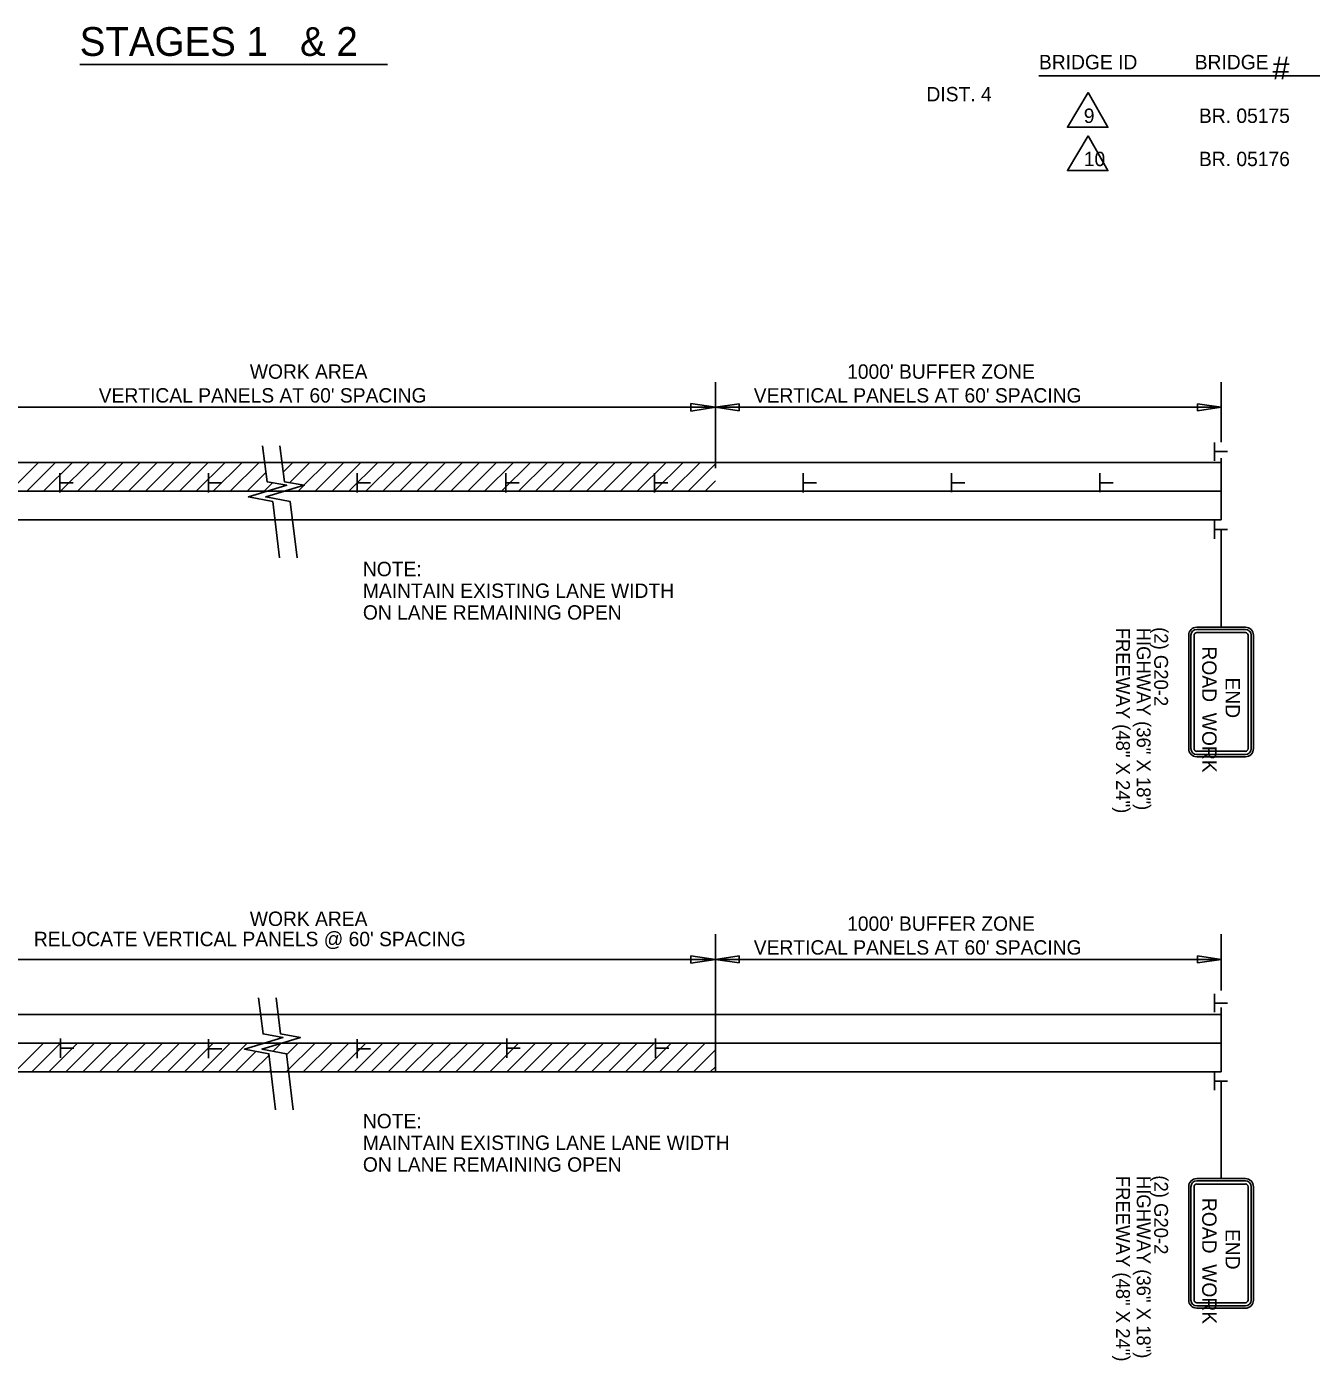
# Model space of a CAD drawing. Extents: x 1930579 to 1937521, y 596183 to 597599.
# Drawn here: x 1935668 to 1936204, y 596332 to 596888 of the extents above; entities that cross this region are included whole.
import ezdxf

# ---------------------------------------------------------------- set-up
doc = ezdxf.new("R2010")
doc.units = 0
for name, color, linetype in [('Default', 7, 'Continuous'), ('P_TC_Signs_Temporary', 7, 'Continuous'), ('R_Annotation', 7, 'Continuous')]:
    doc.layers.add(name, color=color, linetype=linetype)

msp = doc.modelspace()

# ---------------------------------------------------------------- linework, layer by layer
at = {"layer": 'Default'}
for p, q in [((1935690.44, 596872.49), (1935818.76, 596872.49)), ((1935955.49, 596740.12), (1935955.49, 596704.24)), ((1936166.23, 596740.12), (1936166.23, 596715.05)), ((1935955.49, 596729.59), (1935620.14, 596729.59)), ((1935945.19, 596728.04), (1935945.19, 596731.13)), ((1935945.19, 596731.13), (1935955.49, 596729.59)), ((1935955.49, 596729.59), (1935945.19, 596728.04)), ((1935955.49, 596729.59), (1935965.38, 596731.08)), ((1936166.23, 596729.59), (1935955.49, 596729.59)), ((1935965.38, 596728.11), (1935955.49, 596729.59)), ((1935965.38, 596731.08), (1935965.38, 596728.11)), ((1936156.33, 596728.11), (1936156.33, 596731.08)), ((1936156.33, 596731.08), (1936166.23, 596729.59)), ((1936156.33, 596728.11), (1936156.33, 596731.08)), ((1936156.33, 596731.08), (1936166.23, 596729.59)), ((1936166.23, 596729.59), (1936156.33, 596728.11)), ((1936166.23, 596729.59), (1936156.33, 596728.11)), ((1936163.5, 596714.95), (1936163.5, 596707.29)), ((1936163.61, 596711.14), (1936168.84, 596711.14)), ((1936166.23, 596706.66), (1935116.21, 596706.66)), ((1935661.26, 596694.66), (1935673.26, 596706.66)), ((1935668.34, 596694.66), (1935680.34, 596706.66)), ((1935675.41, 596694.66), (1935687.41, 596706.66)), ((1935682.48, 596694.66), (1935694.48, 596706.66)), ((1935689.55, 596694.66), (1935701.55, 596706.66)), ((1935696.62, 596694.66), (1935708.62, 596706.66)), ((1935703.69, 596694.66), (1935715.69, 596706.66)), ((1935710.76, 596694.66), (1935722.76, 596706.66)), ((1935717.83, 596694.66), (1935729.83, 596706.66)), ((1935724.9, 596694.66), (1935736.9, 596706.66)), ((1935731.98, 596694.66), (1935743.98, 596706.66)), ((1935739.05, 596694.66), (1935751.05, 596706.66)), ((1935746.12, 596694.66), (1935758.12, 596706.66)), ((1935753.19, 596694.66), (1935765.19, 596706.66)), ((1935775.29, 596702.63), (1935779.33, 596706.66)), ((1935777.92, 596698.18), (1935786.4, 596706.66)), ((1935783.93, 596697.11), (1935793.47, 596706.66)), ((1935788.54, 596694.66), (1935800.54, 596706.66)), ((1935795.62, 596694.66), (1935807.62, 596706.66)), ((1935802.69, 596694.66), (1935814.69, 596706.66)), ((1935809.76, 596694.66), (1935821.76, 596706.66)), ((1935816.83, 596694.66), (1935828.83, 596706.66)), ((1935823.9, 596694.66), (1935835.9, 596706.66)), ((1935830.97, 596694.66), (1935842.97, 596706.66)), ((1935838.04, 596694.66), (1935850.04, 596706.66)), ((1935845.11, 596694.66), (1935857.11, 596706.66)), ((1935852.18, 596694.66), (1935864.18, 596706.66)), ((1935859.25, 596694.66), (1935871.25, 596706.66)), ((1935866.33, 596694.66), (1935878.33, 596706.66)), ((1935873.4, 596694.66), (1935885.4, 596706.66)), ((1935880.47, 596694.66), (1935892.47, 596706.66)), ((1935887.54, 596694.66), (1935899.54, 596706.66)), ((1935894.61, 596694.66), (1935906.61, 596706.66)), ((1935901.68, 596694.66), (1935913.68, 596706.66)), ((1935908.75, 596694.66), (1935920.75, 596706.66)), ((1935915.82, 596694.66), (1935927.82, 596706.66)), ((1935922.89, 596694.66), (1935934.89, 596706.66)), ((1935929.97, 596694.66), (1935941.97, 596706.66)), ((1935937.04, 596694.66), (1935949.04, 596706.66)), ((1935944.11, 596694.66), (1935955.49, 596706.05)), ((1936166.23, 596708.38), (1936166.23, 596682.66)), ((1935682.13, 596694.12), (1935682.13, 596702.1)), ((1935744.13, 596694.12), (1935744.13, 596702.1)), ((1935760.26, 596694.66), (1935768.03, 596702.44)), ((1935806.12, 596694.12), (1935806.12, 596702.1)), ((1935868.11, 596694.12), (1935868.11, 596702.1)), ((1935930.1, 596694.12), (1935930.1, 596702.1)), ((1935991.98, 596694.14), (1935991.98, 596702.12)), ((1936053.85, 596694.17), (1936053.85, 596702.15)), ((1936115.73, 596694.19), (1936115.73, 596702.17)), ((1935116.21, 596694.66), (1936166.23, 596694.66)), ((1935682.25, 596698.09), (1935687.7, 596698.09)), ((1935744.24, 596698.09), (1935749.69, 596698.09)), ((1935767.33, 596694.66), (1935770.81, 596698.14)), ((1935781.47, 596694.66), (1935783.83, 596697.02)), ((1935806.24, 596698.09), (1935811.68, 596698.09)), ((1935868.23, 596698.09), (1935873.67, 596698.09)), ((1935930.22, 596698.09), (1935935.67, 596698.09)), ((1935951.18, 596694.66), (1935955.49, 596698.97)), ((1935992.09, 596698.11), (1935997.54, 596698.11)), ((1936053.97, 596698.13), (1936059.42, 596698.13)), ((1936115.84, 596698.16), (1936121.29, 596698.16)), ((1936166.23, 596682.66), (1935116.21, 596682.66)), ((1935619.93, 596682.66), (1935770.53, 596682.66)), ((1935778.18, 596682.66), (1935955.49, 596682.66)), ((1936163.5, 596682.43), (1936163.5, 596674.76)), ((1936163.61, 596678.62), (1936168.84, 596678.62)), ((1935955.49, 596510.03), (1935955.49, 596452.57)), ((1935955.49, 596510.03), (1935955.49, 596474.15)), ((1936166.23, 596510.03), (1936166.23, 596486.53)), ((1935945.19, 596497.95), (1935945.19, 596501.04)), ((1935945.19, 596501.04), (1935955.49, 596499.5)), ((1935955.49, 596499.5), (1935965.38, 596500.98)), ((1935965.38, 596500.98), (1935965.38, 596498.01)), ((1936156.33, 596498.01), (1936156.33, 596500.98)), ((1936156.33, 596500.98), (1936166.23, 596499.5)), ((1936156.33, 596498.01), (1936156.33, 596500.98)), ((1936156.33, 596500.98), (1936166.23, 596499.5)), ((1935955.49, 596499.5), (1935620.14, 596499.5)), ((1935955.49, 596499.5), (1935945.19, 596497.95)), ((1936166.23, 596499.5), (1935955.49, 596499.5)), ((1935965.38, 596498.01), (1935955.49, 596499.5)), ((1936166.23, 596499.5), (1936156.33, 596498.01)), ((1936166.23, 596499.5), (1936156.33, 596498.01)), ((1936163.5, 596485.1), (1936163.5, 596477.44)), ((1936163.61, 596481.3), (1936168.84, 596481.3)), ((1936166.23, 596479.48), (1936166.23, 596452.57)), ((1936166.23, 596476.57), (1935116.21, 596476.57)), ((1935682.46, 596458.49), (1935682.46, 596466.46)), ((1935868.43, 596458.49), (1935868.43, 596466.46)), ((1935930.42, 596458.49), (1935930.42, 596466.46)), ((1935116.21, 596464.57), (1936166.23, 596464.57)), ((1935663.41, 596452.57), (1935675.41, 596464.57)), ((1935670.48, 596452.57), (1935682.48, 596464.57)), ((1935677.55, 596452.57), (1935689.55, 596464.57)), ((1935682.57, 596462.45), (1935688.02, 596462.45)), ((1935684.62, 596452.57), (1935696.62, 596464.57)), ((1935691.69, 596452.57), (1935703.69, 596464.57)), ((1935698.76, 596452.57), (1935710.76, 596464.57)), ((1935705.83, 596452.57), (1935717.83, 596464.57)), ((1935712.9, 596452.57), (1935724.9, 596464.57)), ((1935719.98, 596452.57), (1935731.98, 596464.57)), ((1935727.05, 596452.57), (1935739.05, 596464.57)), ((1935734.12, 596452.57), (1935746.12, 596464.57)), ((1935741.19, 596452.57), (1935753.19, 596464.57)), ((1935744.13, 596458.29), (1935744.13, 596466.27)), ((1935744.24, 596462.26), (1935749.69, 596462.26)), ((1935748.26, 596452.57), (1935760.26, 596464.57)), ((1935755.33, 596452.57), (1935763.97, 596461.21)), ((1935771.08, 596461.25), (1935774.4, 596464.57)), ((1935776.54, 596452.57), (1935788.54, 596464.57)), ((1935776.65, 596459.74), (1935781.47, 596464.57)), ((1935783.62, 596452.57), (1935795.62, 596464.57)), ((1935790.69, 596452.57), (1935802.69, 596464.57)), ((1935797.76, 596452.57), (1935809.76, 596464.57)), ((1935804.83, 596452.57), (1935816.83, 596464.57)), ((1935806.12, 596458.29), (1935806.12, 596466.27)), ((1935806.24, 596462.26), (1935811.68, 596462.26)), ((1935811.9, 596452.57), (1935823.9, 596464.57)), ((1935818.97, 596452.57), (1935830.97, 596464.57)), ((1935826.04, 596452.57), (1935838.04, 596464.57)), ((1935833.11, 596452.57), (1935845.11, 596464.57)), ((1935840.18, 596452.57), (1935852.18, 596464.57)), ((1935847.25, 596452.57), (1935859.25, 596464.57)), ((1935854.33, 596452.57), (1935866.33, 596464.57)), ((1935861.4, 596452.57), (1935873.4, 596464.57)), ((1935868.47, 596452.57), (1935880.47, 596464.57)), ((1935868.55, 596462.45), (1935874, 596462.45)), ((1935875.54, 596452.57), (1935887.54, 596464.57)), ((1935882.61, 596452.57), (1935894.61, 596464.57)), ((1935889.68, 596452.57), (1935901.68, 596464.57)), ((1935896.75, 596452.57), (1935908.75, 596464.57)), ((1935903.82, 596452.57), (1935915.82, 596464.57)), ((1935910.89, 596452.57), (1935922.89, 596464.57)), ((1935917.97, 596452.57), (1935929.97, 596464.57)), ((1935925.04, 596452.57), (1935937.04, 596464.57)), ((1935930.54, 596462.45), (1935935.99, 596462.45)), ((1935932.11, 596452.57), (1935944.11, 596464.57)), ((1935939.18, 596452.57), (1935951.18, 596464.57)), ((1935946.25, 596452.57), (1935955.49, 596461.81)), ((1935762.4, 596452.57), (1935769.39, 596459.55)), ((1936166.23, 596452.57), (1935116.21, 596452.57)), ((1935619.93, 596452.57), (1935770.53, 596452.57)), ((1935769.47, 596452.57), (1935770.14, 596453.24)), ((1935778.18, 596452.57), (1935955.49, 596452.57)), ((1935953.32, 596452.57), (1935955.49, 596454.74)), ((1936163.5, 596452.58), (1936163.5, 596444.92)), ((1936163.61, 596448.77), (1936168.84, 596448.77))]:
    msp.add_line(p, q, dxfattribs=at)
for points in [[(1935766.64, 596713.56), (1935768.52, 596698.55), (1935776.78, 596697.09), (1935760.75, 596692.23), (1935770.95, 596690.29), (1935773.76, 596666.9)], [(1935773.93, 596713.56), (1935775.8, 596698.55), (1935784.06, 596697.09), (1935768.03, 596692.23), (1935778.23, 596690.29), (1935781.05, 596666.9)], [(1935765, 596483.47), (1935766.88, 596468.46), (1935775.14, 596467), (1935759.11, 596462.14), (1935769.31, 596460.2), (1935772.12, 596436.81)], [(1935772.29, 596483.47), (1935774.16, 596468.46), (1935782.42, 596467), (1935766.39, 596462.14), (1935776.59, 596460.2), (1935779.41, 596436.81)]]:
    msp.add_lwpolyline(points, dxfattribs=at)
at = {"layer": 'P_TC_Signs_Temporary'}
for p, q in [((1936152.73, 596634.59), (1936152.73, 596587.34)), ((1936153.66, 596634.59), (1936153.66, 596587.34)), ((1936154.98, 596634.59), (1936154.98, 596587.34)), ((1936176.35, 596637.97), (1936156.1, 596637.97)), ((1936176.35, 596637.03), (1936156.1, 596637.03)), ((1936176.35, 596635.72), (1936156.1, 596635.72)), ((1936177.48, 596587.34), (1936177.48, 596634.59)), ((1936178.79, 596587.34), (1936178.79, 596634.59)), ((1936179.73, 596587.34), (1936179.73, 596634.59)), ((1936156.1, 596586.22), (1936176.35, 596586.22)), ((1936156.1, 596584.9), (1936176.35, 596584.9)), ((1936156.1, 596583.97), (1936176.35, 596583.97)), ((1936176.35, 596408.12), (1936156.1, 596408.12)), ((1936176.35, 596407.18), (1936156.1, 596407.18)), ((1936176.35, 596405.87), (1936156.1, 596405.87)), ((1936152.73, 596404.75), (1936152.73, 596357.5)), ((1936153.66, 596404.75), (1936153.66, 596357.5)), ((1936154.98, 596404.75), (1936154.98, 596357.5)), ((1936177.48, 596357.5), (1936177.48, 596404.75)), ((1936178.79, 596357.5), (1936178.79, 596404.75)), ((1936179.73, 596357.5), (1936179.73, 596404.75)), ((1936156.1, 596356.37), (1936176.35, 596356.37)), ((1936156.1, 596355.06), (1936176.35, 596355.06)), ((1936156.1, 596354.12), (1936176.35, 596354.12))]:
    msp.add_line(p, q, dxfattribs=at)
for centre, radius, start, end in [((1936156.1, 596634.59), 3.37, 90, 180), ((1936156.1, 596634.59), 2.44, 90, 180), ((1936156.1, 596634.59), 1.13, 90, 180), ((1936176.35, 596634.59), 3.37, 360, 90), ((1936176.35, 596634.59), 2.44, 360, 90), ((1936176.35, 596634.59), 1.13, 360, 90), ((1936156.1, 596587.34), 3.37, 180, 270), ((1936156.1, 596587.34), 2.44, 180, 270), ((1936156.1, 596587.34), 1.13, 180, 270), ((1936176.35, 596587.34), 2.44, 270, 360), ((1936176.35, 596587.34), 1.13, 270, 360), ((1936176.35, 596587.34), 3.38, 270, 360), ((1936156.1, 596404.75), 3.37, 90, 180), ((1936156.1, 596404.75), 2.44, 90, 180), ((1936156.1, 596404.75), 1.13, 90, 180), ((1936176.35, 596404.75), 3.37, 360, 90), ((1936176.35, 596404.75), 2.44, 360, 90), ((1936176.35, 596404.75), 1.13, 360, 90), ((1936156.1, 596357.5), 3.37, 180, 270), ((1936156.1, 596357.5), 2.44, 180, 270), ((1936156.1, 596357.5), 1.13, 180, 270), ((1936176.35, 596357.5), 2.44, 270, 360), ((1936176.35, 596357.5), 1.13, 270, 360), ((1936176.35, 596357.5), 3.38, 270, 360)]:
    msp.add_arc(centre, radius, start, end, dxfattribs=at)
at = {"layer": 'R_Annotation'}
for p, q in [((1936090.31, 596867.77), (1936637.5, 596867.77)), ((1936166.23, 596637.97), (1936166.23, 596678.62)), ((1936166.23, 596408.12), (1936166.23, 596448.77))]:
    msp.add_line(p, q, dxfattribs=at)
for points in [[(1936110.88, 596860.76), (1936102.16, 596846.29), (1936119.05, 596846.29), (1936110.88, 596860.76)], [(1936110.88, 596842.76), (1936102.16, 596828.29), (1936119.05, 596828.29), (1936110.88, 596842.76)]]:
    msp.add_lwpolyline(points, dxfattribs=at)

# ---------------------------------------------------------------- texts
at = {"layer": 'Default'}
for s, height, p in [('STAGES 1   & 2', 12, (1935690.44, 596876.06)), ('WORK AREA', 6, (1935761.36, 596741.5)), ("1000' BUFFER ZONE", 6, (1936010.35, 596741.5)), ("VERTICAL PANELS AT 60' SPACING", 5.9999, (1935698.38, 596731.57)), ("VERTICAL PANELS AT 60' SPACING", 5.9999, (1935971.43, 596731.57)), ('WORK AREA', 6, (1935761.36, 596513.43)), ("1000' BUFFER ZONE", 6, (1936010.35, 596511.41)), ("RELOCATE VERTICAL PANELS @ 60' SPACING", 6, (1935671.34, 596505)), ("VERTICAL PANELS AT 60' SPACING", 5.9999, (1935971.43, 596501.48))]:
    msp.add_text(s, height=height, rotation=360, dxfattribs=at).set_placement(p)
at = {"layer": 'P_TC_Signs_Temporary'}
for s, p in [('ROAD  WORK', (1936158.35, 596629.93)), ('END', (1936168.1, 596617)), ('ROAD  WORK', (1936158.35, 596400.08)), ('END', (1936168.1, 596387.15))]:
    msp.add_text(s, height=6, rotation=270, dxfattribs=at).set_placement(p)
at = {"layer": 'R_Annotation'}
for s, height, rotation, p in [('BRIDGE ID', 6, 360, (1936090.31, 596870.47)), ('BRIDGE ', 6, 360, (1936155.25, 596870.47)), ('#', 9.6, 360, (1936187.67, 596866.23)), ('DIST. 4', 6, 360, (1936043.41, 596857.12)), ('9', 6, 360, (1936109, 596848.12)), ('BR. 05175', 6, 360, (1936157, 596848.12)), ('10', 6, 360, (1936109, 596830.12)), ('BR. 05176', 6, 360, (1936157, 596830.12)), ('NOTE:', 6, 360, (1935808.49, 596659.2)), ('MAINTAIN EXISTING LANE WIDTH', 6, 360, (1935808.49, 596650.15)), ('ON LANE REMAINING OPEN', 6, 360, (1935808.49, 596641.1)), ('FREEWAY (48" X 24")', 5.76, 270, (1936122.46, 596637.76)), ('HIGHWAY (36" X 18")', 5.76, 270, (1936131.1, 596637.76)), ('(2) G20-2', 5.76, 270, (1936138.35, 596637.97)), ('NOTE:', 6, 360, (1935808.49, 596429.11)), ('MAINTAIN EXISTING LANE LANE WIDTH', 6, 360, (1935808.49, 596420.06)), ('ON LANE REMAINING OPEN', 6, 360, (1935808.49, 596411.01)), ('FREEWAY (48" X 24")', 5.76, 270, (1936122.46, 596409.29)), ('HIGHWAY (36" X 18")', 5.76, 270, (1936131.1, 596409.29)), ('(2) G20-2', 5.76, 270, (1936138.35, 596409.49))]:
    msp.add_text(s, height=height, rotation=rotation, dxfattribs=at).set_placement(p)

doc.saveas('drawing.dxf')
